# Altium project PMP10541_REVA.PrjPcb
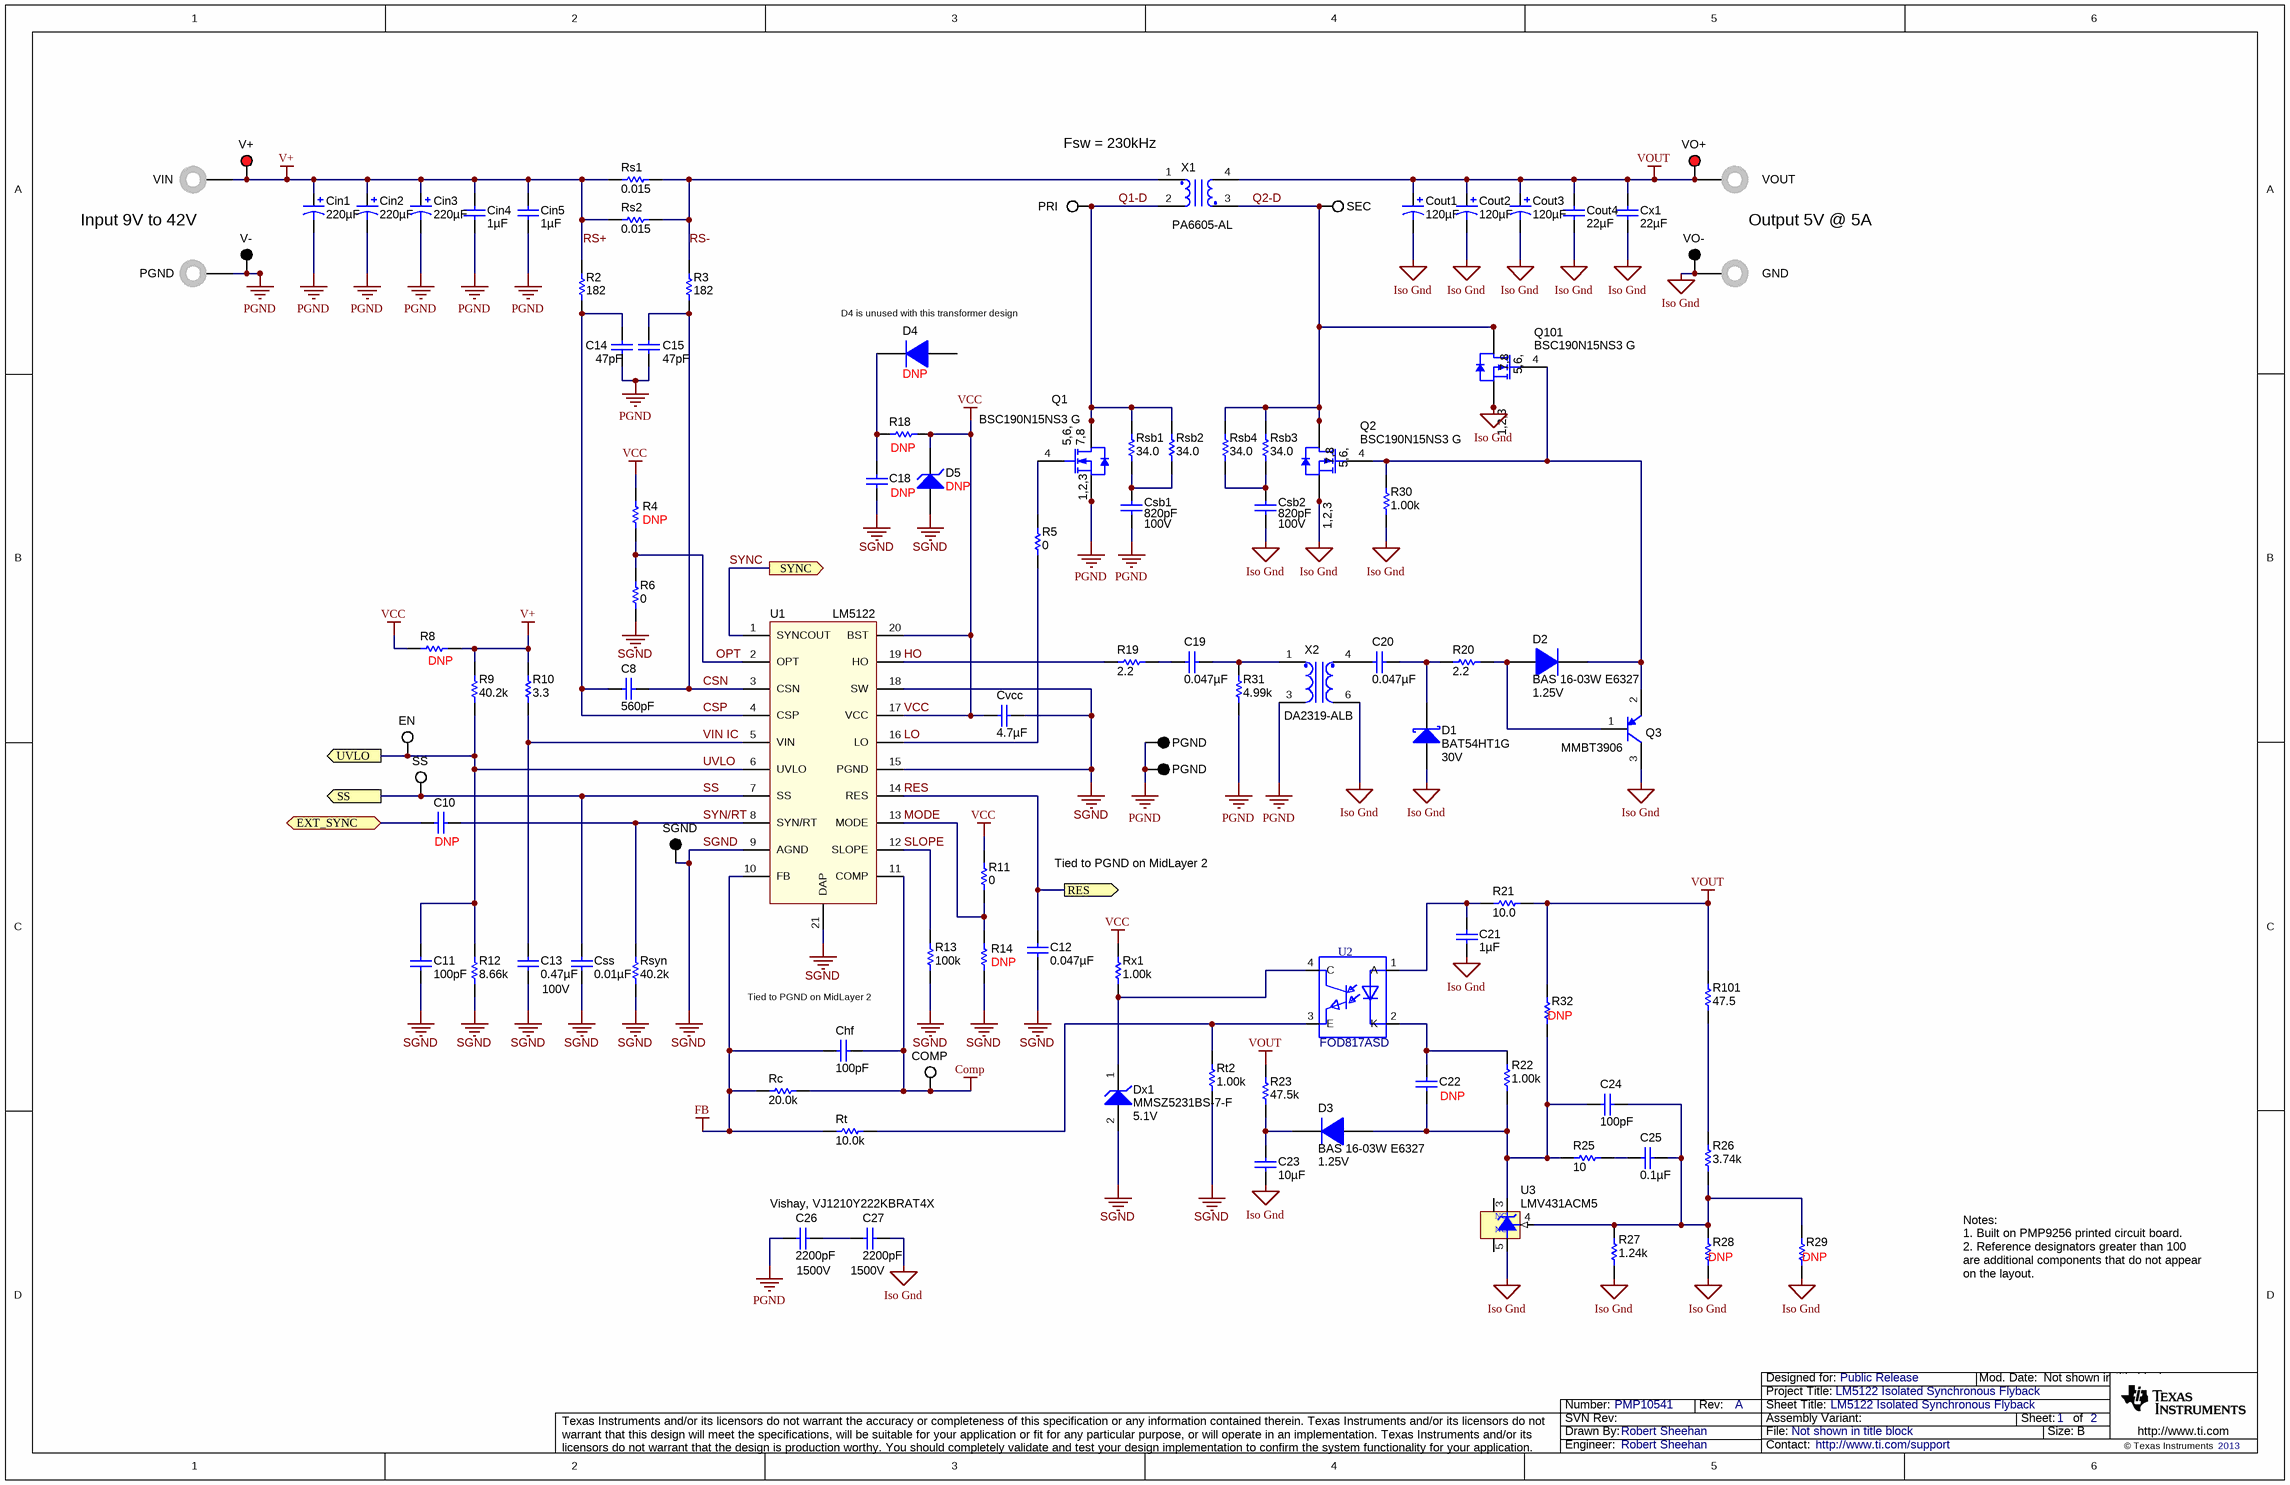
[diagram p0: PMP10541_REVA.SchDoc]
CopyrightYear: 2013; PCB_Layout: Jacen Schaedler; PCB_Rev: E1; PRJ_Customer: Public Release; PRJ_Engineer: Robert Sheehan; PRJ_Number: PMP10541; PRJ_Title: LM5122 Isolated Synchronous Flyback; SCH_Rev: A; TechSupport: http://www.ti.com/support
2 sheets, 118 parts. Net scope: flat (ports and power ports of the same name join across sheets).
Board file: PMP9256 Rev3.PcbDoc
Sheets:
  PMP10541_REVA.SchDoc
  Hardware_ANSI-B.SchDoc

## Sheet PMP10541_REVA.SchDoc: LM5122 Isolated Synchronous Flyback
size 431 x 279 mm; Date: Not shown in title block; ApprovedBy: David Baba; CheckedBy: Not shown in title block; Author: Not shown in title block; CompanyName: Not shown in title block; DrawnBy: Robert Sheehan; Engineer: Robert Sheehan; Organization: Not shown in title block; Address1: Not shown in title block; Address2: Not shown in title block; Address3: Not shown in title block; Address4: Not shown in title block; DocumentNumber: 1; Revision: Use project parameter SCH_Rev; SheetNumber: 1; SheetTotal: 2; PageSetup: Record=PageOptions¦CenterHorizontal=True¦CenterVertical=True¦PrintScale=0.96¦XCorrection=1.00¦YCorrection=1.00¦PrintKind=0¦BorderSize=5000000¦LeftOffset=0¦BottomOffset=0¦Orientation=2¦PaperLength=1000¦PaperWidth=1000¦Scale=100¦PaperSource=15¦PrintQuality=600¦MediaType=1¦DitherType=10¦PaperKind=11x17¦PrintScaleMode=1

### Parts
C8  ValueDisplayed: 560pF  [0603L]  (hidden comment: GRM1885C1H561JA01D)
C10  DNP  [0603L]
C11  ValueDisplayed: 100pF  [0603L]  (hidden comment: GRM1885C1H101JA01D)
C12  ValueDisplayed: 0.047µF  [0603L]  (hidden comment: GRM188R71E473KA01D)
C13  ValueDisplayed: 0.47µF  Value2: 100V  [0805L]  (hidden comment: GRM21BR72A474KA73L)
C14  ValueDisplayed: 47pF  [0603L]  (hidden comment: GRM1885C1H470JA01D)
C15  ValueDisplayed: 47pF  [0603L]  (hidden comment: GRM1885C1H470JA01D)
C18  DNP  [0805L]
C19  ValueDisplayed: 0.047µF  [0603L]  (hidden comment: GRM188R71E473KA01D)
C20  ValueDisplayed: 0.047µF  [0603L]  (hidden comment: GRM188R71E473KA01D)
C21  ValueDisplayed: 1µF  [0603L]  (hidden comment: C1608X7R1C105K)
C22  DNP  [0805L]
C23  ValueDisplayed: 10µF  [0805L]  (hidden comment: GRM21BR61C106KE15L)
C24  ValueDisplayed: 100pF  [0805L]  (hidden comment: 08051A101FAT2A)
C25  ValueDisplayed: 0.1µF  [0603L]  (hidden comment: GRM188R71H104KA93D)
C26  Vishay, VJ1210Y222KBRAT4X  ValueDisplayed: 2200pF  Value2: 1500V  [1210L]
C27  ValueDisplayed: 2200pF  Value2: 1500V  [1210L]  (hidden comment: VJ1210Y222KXGAT5Z)
Chf  ValueDisplayed: 100pF  [0603L]  (hidden comment: GRM1885C1H101JA01D)
Cin1  ValueDisplayed: 220µF  [SM_RADIAL_H13]  (hidden comment: EEV-FK1J221Q)
Cin2  ValueDisplayed: 220µF  [SM_RADIAL_H13]  (hidden comment: EEV-FK1J221Q)
Cin3  ValueDisplayed: 220µF  [SM_RADIAL_H13]  (hidden comment: EEV-FK1J221Q)
Cin4  ValueDisplayed: 1µF  [1206L]  (hidden comment: C3216X7R2A105M)
Cin5  ValueDisplayed: 1µF  [1206L]  (hidden comment: C3216X7R2A105M)
COMP  5002  [Keystone5002]  (value not drawn)
Cout1  ValueDisplayed: 120µF  [CAPSMT_62_F61]  (hidden comment: 20SVPF120M)
Cout2  ValueDisplayed: 120µF  [CAPSMT_62_F61]  (hidden comment: 20SVPF120M)
Cout3  ValueDisplayed: 120µF  [CAPSMT_62_F61]  (hidden comment: 20SVPF120M)
Cout4  ValueDisplayed: 22µF  [1206L]  (hidden comment: GRM31CR61C226KE15L)
Csb1  ValueDisplayed: 820pF  Value2: 100V  [0603L]  (hidden comment: GRM188R72A821KA01D)
Csb2  ValueDisplayed: 820pF  Value2: 100V  [0603L]  (hidden comment: GRM188R72A821KA01D)
Css  ValueDisplayed: 0.01µF  [0603L]  (hidden comment: GRM188R71H103KA01D)
Cvcc  ValueDisplayed: 4.7µF  [0603L]  (hidden comment: C0603C475K8PACTU)
Cx1  ValueDisplayed: 22µF  [1206L]  (hidden comment: GRM31CR61C226KE15L)
D1  BAT54HT1G  value 30V  [sod-323]
D2  BAS 16-03W E6327  value 1.25V  [sod-323]
D3  BAS 16-03W E6327  value 1.25V  [sod-323]
D4  DNP  [SOD-123]
D5  DNP  [SMA]
Dx1  MMSZ5231BS-7-F  value 5.1V  [sod-323]
EN  5002  [Keystone5002]  (value not drawn)
PGND  GND  [Keystone_575-4]
PGND2  PGND  [Keystone_575-4]
PGND3  PGND  [Keystone5011]
PGND4  PGND  [Keystone5011]
PRI  5002  [Keystone5002]  (value not drawn)
Q1  BSC190N15NS3 G  [PG-TDSON-8]
Q2  BSC190N15NS3 G  [PG-TDSON-8]
Q3  MMBT3906  [SOT-23]
Q101  BSC190N15NS3 G  [PG-TDSON-8]
R2  value 182  [0603L]  (hidden comment: CRCW0603182RFKEA)
R3  value 182  [0603L]  (hidden comment: CRCW0603182RFKEA)
R4  DNP  [0603L]
R5  value 0  [0603L]  (hidden comment: ERJ-3GEY0R00V)
R6  value 0  [0603L]  (hidden comment: ERJ-3GEY0R00V)
R8  DNP  [0603L]
R9  value 40.2k  [0603L]  (hidden comment: CRCW060340K2FKEA)
R10  value 3.3  [0603L]  (hidden comment: CRCW06033R30JNEA)
R11  value 0  [0603L]  (hidden comment: ERJ-3GEY0R00V)
R12  value 8.66k  [0603L]  (hidden comment: CRCW06038K66FKEA)
R13  value 100k  [0603L]  (hidden comment: CRCW0603100KFKEA)
R14  DNP  [0603L]
R18  DNP  [0603L]
R19  value 2.2  [0603L]  (hidden comment: CRCW06032R20JNEA)
R20  value 2.2  [0603L]  (hidden comment: CRCW06032R20JNEA)
R21  value 10.0  [0805L]  (hidden comment: CRCW080510R0FKEA)
R22  ValueDisplayed: 1.00k  [0603L]  (hidden comment: CRCW06031K00FKEA)
R23  value 47.5k  [0603L]  (hidden comment: CRCW060347K5FKEA)
R25  ValueDisplayed: 10  [0603L]  (hidden comment: CRCW060310R0JNEA)
R26  ValueDisplayed: 3.74k  [0603L]  (hidden comment: CRCW06033K74FKEA)
R27  ValueDisplayed: 1.24k  [0603L]  (hidden comment: CRCW06031K24FKEA)
R28  DNP  [0603L]
R29  DNP  [0603L]
R30  value 1.00k  [0603L]  (hidden comment: CRCW06031K00FKEA)
R31  value 4.99k  [0603L]  (hidden comment: CRCW06034K99FKEA)
R32  DNP  [0603L]
R101  ValueDisplayed: 47.5  [0603]  (hidden comment: CRCW060347R5FKEA)
Rc  value 20.0k  [0603L]  (hidden comment: CRCW060320K0FKEA)
Rs1  ValueDisplayed: 0.015  [2512]  (hidden comment: WSL2512R0150FEA)
Rs2  ValueDisplayed: 0.015  [2512]  (hidden comment: WSL2512R0150FEA)
Rsb1  value 34.0  [1210L]  (hidden comment: ERJ-14NF34R0U)
Rsb2  value 34.0  [1210L]  (hidden comment: ERJ-14NF34R0U)
Rsb3  value 34.0  [1210L]  (hidden comment: ERJ-14NF34R0U)
Rsb4  value 34.0  [1210L]  (hidden comment: ERJ-14NF34R0U)
Rsyn  value 40.2k  [0603L]  (hidden comment: CRCW060340K2FKEA)
Rt  value 10.0k  [0603L]  (hidden comment: CRCW060310K0FKEA)
Rt2  value 1.00k  [0603L]  (hidden comment: CRCW06031K00FKEA)
Rx1  value 1.00k  [0603L]  (hidden comment: CRCW06031K00FKEA)
SEC  5002  [Keystone5002]  (value not drawn)
SGND  SGND  [Keystone5001]  (value not drawn)
SS  5002  [Keystone5002]  (value not drawn)
U1  LM5122  [MXA20A_L]
U2  FOD817ASD  [FOD817AS]
U3  TI, LMV431ACM5  [MF05A_N]  (value not drawn)
V+  5010  [Keystone5010]  (value not drawn)
V-  5011  [Keystone5011]  (value not drawn)
VIN  575-4  [Keystone_575-4]  (value not drawn)
VO+  5010  [Keystone5010]  (value not drawn)
VO-  5011  [Keystone5011]  (value not drawn)
VOUT  Comment_1: Output 5V @ 5A  [Keystone_575-4]  (hidden comment: 575-4)
X1  PA6605-AL  [PA6605-AL]
X2  DA2319-ALB  [DA2319-ALB]

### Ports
EXT_SYNC, RES, SS, SYNC (out), UVLO

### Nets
Comp: Chf.1 COMP.1 Rc.2 U1.11(COMP)
FB: Chf.2 Rc.1 Rt.2 U1.10(FB)
Iso Gnd: C21.2 C23.2 C27.1 Cout1.2(-) Cout2.2(-) Cout3.2(-) Cout4.2 Csb2.2 Cx1.2 D1.2(A) PGND.1 Q2.1(S) Q2.2(S) Q2.3(S) Q3.3(C) Q101.1(S) Q101.2(S) Q101.3(S) R27.1 R28.1 R29.1 R30.1 U3.5(A) VO-.1 X2.6
PGND: C11.2 C12.2 C13.2 C14.1 C15.2 C18.2 C26.2 Cin1.2(-) Cin2.2(-) Cin3.2(-) Cin4.2 Cin5.2 Csb1.2 Css.2 Cvcc.1 D5.2(A) Dx1.2(A) PGND2.1 PGND3.1 PGND4.1 Q1.1(S) Q1.2(S) Q1.3(S) R6.1 R12.1 R13.1 R14.1 R31.1 Rsyn.1 Rt2.1 SGND.1 U1.9(AGND) U1.15(PGND) U1.18(SW) U1.21(DAP) V-.1 X2.3
V+: Cin1.1(+) Cin2.1(+) Cin3.1(+) Cin4.1 Cin5.1 R2.2 R8.1 R9.2 R10.2 Rs1.1 Rs2.1 V+.1 VIN.1
VCC: Cvcc.2 D5.1(K) R4.2 R8.2 R11.2 R18.1 Rx1.2 U1.17(VCC) U1.20(BST)
VOUT: Cout1.1(+) Cout2.1(+) Cout3.1(+) Cout4.1 Cx1.1 R21.2 R23.2 R32.1 R101.2 VO+.1 VOUT.1 X1.4
CSN: C8.1 C15.1 R3.1 U1.3(CSN)
CSP: C8.2 C14.2 R2.1 U1.4(CSP)
EXT_SYNC: C10.2 ; port EXT_SYNC
HO: R19.2 U1.19(HO)
LO: R5.2 U1.16(LO)
MODE: R11.1 R14.2 U1.13(MODE)
OPT: R4.1 R6.2 U1.2(OPT)
Q1-D: PRI.1 Q1.5(D) Q1.6(D) Q1.7(D) Q1.8(D) Q1.9(D) Rsb1.2 Rsb2.2 X1.2
Q2-D: Q2.5(D) Q2.6(D) Q2.7(D) Q2.8(D) Q2.9(D) Q101.5(D) Q101.6(D) Q101.7(D) Q101.8(D) Q101.9(D) Rsb3.2 Rsb4.2 SEC.1 X1.3
RES: C12.1 U1.14(RES) ; port RES
RS-: R3.2 Rs1.2 Rs2.2 X1.1
SLOPE: R13.2 U1.12(SLOPE)
SS: Css.1 SS.1 U1.7(SS) ; port SS
SYN/RT: C10.1 Rsyn.2 U1.8(SYN/RT)
SYNC: U1.1(SYNCOUT) ; port SYNC
UVLO: C11.1 EN.1 R9.1 R12.2 U1.6(UVLO) ; port UVLO
VIN IC: C13.1 R10.1 U1.5(VIN)
NetC18_1: C18.1 D4.1(K) R18.2
NetC19_1: C19.1 R19.1
NetC19_2: C19.2 R31.2 X2.1
NetC20_1: C20.1 X2.4
NetC20_2: C20.2 D1.1(K) R20.1
NetC21_1: C21.1 R21.1 U2.1(A)
NetC22_1: C22.1 C24.1 D3.2(A) R22.1 R25.1 R32.2 U3.3(K)
NetC22_2: C22.2 R22.2 U2.2(K)
NetC23_1: C23.1 D3.1(K) R23.1
NetC24_2: C24.2 C25.1 R26.1 R27.2 R28.2 R29.2 U3.4(REF)
NetC25_2: C25.2 R25.2
NetC26_1: C26.1 C27.2
NetCsb1_1: Csb1.1 Rsb1.1 Rsb2.1
NetCsb2_1: Csb2.1 Rsb3.1 Rsb4.1
NetD2_1: D2.1(K) Q2.4(G) Q3.2(E) Q101.4(G) R30.2
NetD2_2: D2.2(A) Q3.1(B) R20.2
NetDx1_1: Dx1.1(K) Rx1.1 U2.4(C)
NetQ1_4: Q1.4(G) R5.1
NetR26_2: R26.2 R101.1
NetRt_1: Rt.1 Rt2.2 U2.3(E)

Not connected (* = marked no-connect by the designer): D4 2(A); U3 1(NC) 2(NC)

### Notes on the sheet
- (near X1) Fsw = 230kHz
- Input 9V to 42V
- RS+
- (near D4) D4 is unused with this transformer design
- SGND
- Tied to PGND on MidLayer 2
- (near COMP) SGND
- Notes:
  1. Built on PMP9256 printed circuit board.
  2. Reference designators greater than 100 are additional components that do not appear on the layout.

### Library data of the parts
C8 = GRM1885C1H561JA01D: CAP, CERM, 560pF, 50V, +/-5%, C0G/NP0, 0603; Manufacturer: MuRata; Polarized: N; CompType: Capacitor; U/M: EA; Cap_F: 0.00000000056; Tolerance_%: 5; Value1: Unknown; VDC_V: 50; TaMin_C: -55; TaMax_C: 125; Cap_Case: 0603
C10 = GRM1885C1H101JA01D: CAP, CERM, 100 pF, 50 V, +/- 5%, C0G/NP0, 0603; Manufacturer: MuRata; Polarized: N; CompType: Capacitor; Value: 100pF; U/M: EA; Cap_F: 0.0000000001; Tolerance_%: 5; Value1: Unknown; VDC_V: 50; Value2: 50V; TaMin_C: -55; TaMax_C: 125; Cap_Case: 0603
C11 Chf = GRM1885C1H101JA01D: CAP, CERM, 100pF, 50V, +/-5%, C0G/NP0, 0603; Manufacturer: MuRata; Polarized: N; CompType: Capacitor; U/M: EA; Cap_F: 0.0000000001; Tolerance_%: 5; VDC_V: 50; TaMin_C: -55; TaMax_C: 125; Cap_Case: 0603
C12 C19 C20 = GRM188R71E473KA01D: CAP, CERM, 0.047uF, 25V, +/-10%, X7R, 0603; Manufacturer: MuRata; Polarized: N; CompType: Capacitor; U/M: EA; Cap_F: 0.000000047; Tolerance_%: 10; VDC_V: 25; TaMin_C: -55; TaMax_C: 125; Cap_Case: 0603
C13 = GRM21BR72A474KA73L: CAP, CERM, 0.47uF, 100V, +/-10%, X7R, 0805; Manufacturer: MuRata; Polarized: N; CompType: Capacitor; U/M: EA; Cap_F: 0.00000047; Tolerance_%: 10; Value1: Unknown; VDC_V: 100; TaMin_C: -55; TaMax_C: 125; Cap_Case: 0805
C14 C15 = GRM1885C1H470JA01D: CAP, CERM, 47pF, 50V, +/-5%, C0G/NP0, 0603; Manufacturer: MuRata; Polarized: N; CompType: Capacitor; U/M: EA; Cap_F: 0.000000000047; Tolerance_%: 5; Value1: Unknown; VDC_V: 50; TaMin_C: -55; TaMax_C: 125; Cap_Case: 0603
C18 = GRM21BR61C106KE15L: CAP, CERM, 10uF, 16V, +/-10%, X5R, 0805; Manufacturer: MuRata; Polarized: N; CompType: Capacitor; ValueDisplayed: 10µF; U/M: EA; Cap_F: 0.00001; Tolerance_%: 10; ESR_Ohm: 0.008; Value1: 0.008 ohm; VDC_V: 16; TaMin_C: -55; TaMax_C: 85; Cap_Case: 0805
C21 = C1608X7R1C105K: CAP, CERM, 1uF, 16V, +/-10%, X7R, 0603; Manufacturer: TDK; Polarized: N; CompType: Capacitor; U/M: EA; Cap_F: 0.000001; Tolerance_%: 10; ESR_Ohm: 0.0057; Value1: 0.0057 ohm; VDC_V: 16; TaMin_C: -55; TaMax_C: 125; Cap_Case: 0603
C22 = C2012Y5V1H105Z: Capacitor; Manufacturer: TDK; Cap_Case: 0805; Polarized: N; Tolerance_%: 80; VDC_V: 50; Cap_F: 1.0E-6; Value: 100pF; Value1: Ohm; Value2: 50V; Dielectric: Y5V
C23 = GRM21BR61C106KE15L: CAP, CERM, 10uF, 16V, +/-10%, X5R, 0805; Manufacturer: MuRata; Polarized: N; CompType: Capacitor; U/M: EA; Cap_F: 0.00001; Tolerance_%: 10; ESR_Ohm: 0.008; Value1: 0.008 ohm; VDC_V: 16; TaMin_C: -55; TaMax_C: 85; Cap_Case: 0805
C24 = 08051A101FAT2A: CAP, CERM, 100pF, 100V, +/-1%, C0G/NP0, 0805; Manufacturer: AVX; Polarized: N; CompType: Capacitor; U/M: EA; Cap_F: 0.0000000001; Tolerance_%: 1; ESR_Ohm: 0.356; Value1: 0.356 ohm; VDC_V: 100; TaMin_C: -55; TaMax_C: 125; Cap_Case: 0805
C25 = GRM188R71H104KA93D: CAP, CERM, 0.1uF, 50V, +/-10%, X7R, 0603; Manufacturer: MuRata; Polarized: N; CompType: Capacitor; U/M: EA; Cap_F: 0.0000001; Tolerance_%: 10; Value1: Unknown; VDC_V: 50; TaMin_C: -55; TaMax_C: 125; Cap_Case: 0603
C26 C27 = VJ1210Y222KXGAT5Z: CAP, CERM, 2200pF, 1000V, +/-10%, X7R, 1210; Manufacturer: Vishay-Vitramon; Polarized: N; CompType: Capacitor; U/M: EA; Cap_F: 0.0000000022; Tolerance_%: 10; VDC_V: 1000; TaMin_C: -55; TaMax_C: 125; Cap_Case: 1210
Cin1-Cin3 = EEV-FK1J221Q: CAP, AL, 220uF, 63V, +/-20%, 0.16 ohm, SMD; Manufacturer: Panasonic; Polarized: Y; CompType: Capacitor; U/M: EA; Cap_F: 0.00022; Tolerance_%: 20; VDC_V: 63; ESR_Ohm: 0.16; IRMS_A: 0.8; TaMin_C: -55; TaMax_C: 105; Cap_Case: H13
Cin4 Cin5 = C3216X7R2A105M: CAP, CERM, 1uF, 100V, +/-20%, C Series, 1206; Manufacturer: TDK; Polarized: N; CompType: Capacitor; U/M: EA; Cap_F: 0.000001; Tolerance_%: 20; ESR_Ohm: 0.006; Value1: 0.006 ohm; VDC_V: 100; IRMS_A: 4.5; TaMin_C: -55; TaMax_C: 125; Cap_Case: 1206
COMP EN SS = 5002: Test Point, TH, Miniature, White; Manufacturer: Keystone; CompType: Test Point Loop; U/M: EA
Cout1-Cout3 = 20SVPF120M: CAP, AL, 120uF, 20V, +/-20%, 0.025 ohm, SMD; Manufacturer: Sanyo; Polarized: Y; CompType: Capacitor; U/M: EA; Cap_F: 0.00012; Tolerance_%: 20; ESR_Ohm: 0.025; IRMS_A: 3.2; TaMin_C: -55; TaMax_C: 105
Cout4 Cx1 = GRM31CR61C226KE15L: CAP, CERM, 22uF, 16V, +/-10%, X5R, 1206; Manufacturer: MuRata; Polarized: N; CompType: Capacitor; U/M: EA; Cap_F: 0.000022; Tolerance_%: 10; Value1: Unknown; VDC_V: 16; TaMin_C: -55; TaMax_C: 85; Cap_Case: 1206
Csb1 Csb2 = GRM188R72A821KA01D: CAP, CERM, 820pF, 100V, +/-10%, X7R, 0603; Manufacturer: MuRata; Polarized: N; CompType: Capacitor; U/M: EA; Cap_F: 0.00000000082; Tolerance_%: 10; Value1: Unknown; VDC_V: 100; TaMin_C: -55; TaMax_C: 125; Cap_Case: 0603
Css = GRM188R71H103KA01D: CAP, CERM, 0.01uF, 50V, +/-10%, X7R, 0603; Manufacturer: MuRata; Polarized: N; CompType: Capacitor; U/M: EA; Cap_F: 0.00000001; Tolerance_%: 10; Value1: Unknown; VDC_V: 50; TaMin_C: -55; TaMax_C: 125; Cap_Case: 0603
Cvcc = C0603C475K8PACTU: CAP, CERM, 4.7uF, 10V, +/-10%, X5R, 0603; Manufacturer: Kemet; Polarized: N; CompType: Capacitor; U/M: EA; Cap_F: 0.0000047; Tolerance_%: 10; ESR_Ohm: 0.006; Value1: 0.006 ohm; IRMS_A: 7.24; TaMin_C: -55; TaMax_C: 85; Cap_Case: 0603
D1 = BAT54HT1G: Diode, Schottky, 30V, 0.2A, SOD-323; Manufacturer: ON Semiconductor; U/M: EA; Vf_V: 0.35; Value2: 0.35V; Io_A: 0.2; Vr_V: 30
D2 D3 = Diode: DIODE SWITCH 80V 0.25A SOD323-2; Manufacturer: Infineon Technologies; U/M: EA; Io_A: 0.25; Vf_V: 1.25; Vr_V: 80
D4 = BAV21W-7-F: Diode, Switching, 200V, 0.2A, SOD-123; Manufacturer: Diodes Inc.; U/M: EA; Vf_V: 1.25; Value2: 1.25V; Io_A: 0.2; Vr_V: 200; TJmax_C: 150
D5 = BZG03C15G: Diode, Zener, 15 V, 1.5 W, SMA; Manufacturer: ON Semiconductor; Value: 15V; U/M: EA; Power_W: 1.5; Vz_V: 15; Value1: 1.5W; SymbolCreator: a0412235
Dx1 = MMSZ5231BS-7-F: Diode, Zener, 5.1V, 200mW, SOD-323; Manufacturer: Diodes Inc.; U/M: EA; Power_W: 0.2; Vz_V: 5.1; Value1: 0.2W; RJA_CperW: 350
PGND PGND2 VIN VOUT = 575-4: Standard Banana Jack, Uninsulated, 5.5mm; Manufacturer: Keystone; CompType: Connector; U/M: EA
PGND3 PGND4 V- VO- = 5011: Test Point, TH, Multipurpose, Black; Manufacturer: Keystone; CompType: Test Point Loop; U/M: EA
PRI SEC = 5002: Test Point, Miniature, White, TH; Manufacturer: Keystone; CompType: Test Point Loop; U/M: EA
Q1 Q2 Q101 = BSC190N15NS3 G: MOSFET, N-CH, 150V, 50A, PG-TDSON-8; Manufacturer: Infineon Technologies; Alternate Manufacturer: None; U/M: EA; ChType: N; VdsMax_V: 150; Value1: 0.02 ohm; Rdson45_Ohm: 0.02; Value2: 23 nC; QgTyp_nC: 23; Vgs_V: 20; IdsMax_A: 50
Q3 = MMBT3906, Fairchild Semiconductor: Transistor, PNP, 40V, 0.2A, SOT-23; Alternate Manufacturer: None; CompType: BJT; U/M: EA; PNP: 1; NPN: 0; Vceo_V: 40; Vcesat1_V: 0.25; Value: 0.25V; IcRated_A: 0.2; HfeMax: 300
R2 R3 = CRCW0603182RFKEA: RES, 182 ohm, 1%, 0.1W, 0603; Manufacturer: Vishay-Dale; CompType: Resistor; Value_Code: 182R; Tolerance_%: 1; Power_W: 0.1; VDC_V: 75; TempCo: 100 ppm/C; EIA_Code: E96; U/M: EA
R4 = CRCW0603158KFKEA: RES, 158 k, 1%, 0.1 W, 0603; Manufacturer: Vishay-Dale; CompType: Resistor; Value: 158k; Res_ohm: 158000; Tolerance_%: 1; Power_W: 0.1; Value2: 0.1W; VDC_V: 75; TempCo: 100 ppm/C; EIA_Code: E96; U/M: EA
R5 R6 R11 = ERJ-3GEY0R00V: RES, 0 ohm, 5%, 0.1W, 0603; Manufacturer: Panasonic; CompType: Resistor; Value_Code: 0000; Tolerance_%: 5; Power_W: 0.1; VDC_V: 50; TempCo: 600 ppm/C; EIA_Code: E24; U/M: EA
R8 R14 = ERJ-3GEY0R00V: RES, 0, 5%, 0.1 W, 0603; Manufacturer: Panasonic; CompType: Resistor; Value: 0; Value_Code: 0000; Tolerance_%: 5; Power_W: 0.1; Value2: 0.1W; VDC_V: 50; TempCo: 600 ppm/C; EIA_Code: E24; U/M: EA
R9 Rsyn = CRCW060340K2FKEA: RES, 40.2k ohm, 1%, 0.1W, 0603; Manufacturer: Vishay-Dale; CompType: Resistor; Res_ohm: 40200; Value_Code: 40k2; Tolerance_%: 1; Power_W: 0.1; VDC_V: 75; TempCo: 100 ppm/C; EIA_Code: E96; U/M: EA
R10 = CRCW06033R30JNEA: RES, 3.3 ohm, 5%, 0.1W, 0603; Manufacturer: Vishay-Dale; CompType: Resistor; Value_Code: 3R30; Tolerance_%: 5; Power_W: 0.1; VDC_V: 75; TempCo: 200 ppm/C; EIA_Code: E24; U/M: EA
R12 = CRCW06038K66FKEA: RES, 8.66k ohm, 1%, 0.1W, 0603; Manufacturer: Vishay-Dale; CompType: Resistor; Res_ohm: 8660; Value_Code: 8k66; Tolerance_%: 1; Power_W: 0.1; VDC_V: 75; TempCo: 100 ppm/C; EIA_Code: E96; U/M: EA
R13 = CRCW0603100KFKEA: RES, 100k ohm, 1%, 0.1W, 0603; Manufacturer: Vishay-Dale; CompType: Resistor; Res_ohm: 100000; Tolerance_%: 1; Power_W: 0.1; VDC_V: 75; TempCo: 100 ppm/C; EIA_Code: E96; U/M: EA
R18 = CRCW06030000Z0EA: RES, 0 ohm, 5%, 0.1W, 0603; Manufacturer: Vishay-Dale; Alternate Manufacturer: Any; Alternate PartNumber: Equivalent; CompType: Resistor; Value: 0; Value_Code: 0000; Tolerance_%: 5; Power_W: 0.1; VDC_V: 75; TempCo: 200 ppm/C; EIA_Code: E24; U/M: EA
R19 R20 = CRCW06032R20JNEA: RES, 2.2 ohm, 5%, 0.1W, 0603; Manufacturer: Vishay-Dale; CompType: Resistor; Value_Code: 2R20; Tolerance_%: 5; Power_W: 0.1; VDC_V: 75; TempCo: 200 ppm/C; EIA_Code: E24; U/M: EA
R21 = CRCW080510R0FKEA: RES, 10.0 ohm, 1%, 0.125W, 0805; Manufacturer: Vishay-Dale; CompType: Resistor; Res_ohm: 10; Value_Code: 10R0; Tolerance_%: 1; Power_W: 0.125; VDC_V: 150; TempCo: 100 ppm/C; EIA_Code: E96; U/M: EA
R22 = CRCW06031K00FKEA: RES, 1.00 k, 1%, 0.1 W, 0603; Manufacturer: Vishay-Dale; CompType: Resistor; Value: 1.00k; Res_ohm: 1000; Value_Code: 1k00; Tolerance_%: 1; Power_W: 0.1; Value2: 0.1W; VDC_V: 75; TempCo: 100 ppm/C; EIA_Code: E96; U/M: EA
R23 = CRCW060347K5FKEA: RES, 47.5k ohm, 1%, 0.1W, 0603; Manufacturer: Vishay-Dale; CompType: Resistor; Res_ohm: 47500; Value_Code: 47k5; Tolerance_%: 1; Power_W: 0.1; VDC_V: 75; TempCo: 100 ppm/C; EIA_Code: E96; U/M: EA
R25 = CRCW060310R0JNEA: RES, 10, 5%, 0.1 W, 0603; Manufacturer: Vishay-Dale; CompType: Resistor; Value: 10; Value_Code: 10R0; Tolerance_%: 5; Power_W: 0.1; Value2: 0.1W; VDC_V: 75; TempCo: 200 ppm/C; EIA_Code: E24; U/M: EA
R26 = CRCW06033K74FKEA: RES, 3.74 k, 1%, 0.1 W, 0603; Manufacturer: Vishay-Dale; CompType: Resistor; Value: 3.74k; Res_ohm: 3740; Value_Code: 3k74; Tolerance_%: 1; Power_W: 0.1; Value2: 0.1W; VDC_V: 75; TempCo: 100 ppm/C; EIA_Code: E96; U/M: EA
R27 = CRCW06031K24FKEA: RES, 1.24 k, 1%, 0.1 W, 0603; Manufacturer: Vishay-Dale; CompType: Resistor; Value: 1.24k; Res_ohm: 1240; Value_Code: 1k24; Tolerance_%: 1; Power_W: 0.1; Value2: 0.1W; VDC_V: 75; TempCo: 100 ppm/C; EIA_Code: E96; U/M: EA
R28 = CRCW06032K26FKEA: RES, 2.26k ohm, 1%, 0.1W, 0603; Manufacturer: Vishay-Dale; CompType: Resistor; Res_ohm: 2260; Value_Code: 2k26; Tolerance_%: 1; Power_W: 0.1; VDC_V: 75; TempCo: 100 ppm/C; EIA_Code: E96; U/M: EA
R29 = CRCW0603442RFKEA: RES, 442 ohm, 1%, 0.1W, 0603; Manufacturer: Vishay-Dale; CompType: Resistor; Value: 442; Value_Code: 442R; Tolerance_%: 1; Power_W: 0.1; VDC_V: 75; TempCo: 100 ppm/C; EIA_Code: E96; U/M: EA
R30 Rt2 Rx1 = CRCW06031K00FKEA: RES, 1.00k ohm, 1%, 0.1W, 0603; Manufacturer: Vishay-Dale; CompType: Resistor; Res_ohm: 1000; Value_Code: 1k00; Tolerance_%: 1; Power_W: 0.1; VDC_V: 75; TempCo: 100 ppm/C; EIA_Code: E96; U/M: EA
R31 = CRCW06034K99FKEA: RES, 4.99k ohm, 1%, 0.1W, 0603; Manufacturer: Vishay-Dale; CompType: Resistor; Res_ohm: 4990; Value_Code: 4k99; Tolerance_%: 1; Power_W: 0.1; VDC_V: 75; TempCo: 100 ppm/C; EIA_Code: E96; U/M: EA
R32 Rt = CRCW060310K0FKEA: RES, 10.0k ohm, 1%, 0.1W, 0603; Manufacturer: Vishay-Dale; CompType: Resistor; Res_ohm: 10000; Value_Code: 10k0; Tolerance_%: 1; Power_W: 0.1; VDC_V: 75; TempCo: 100 ppm/C; EIA_Code: E96; U/M: EA
R101 = CRCW060347R5FKEA: RES, 47.5, 1%, 0.1 W, 0603; Manufacturer: Vishay-Dale; CompType: Resistor; Value: 47.5; Value_Code: 47R5; Tolerance_%: 1; Power_W: 0.1; Value2: 0.1W; VDC_V: 75; TempCo: 100 ppm/C; EIA_Code: E96; U/M: EA
Rc = CRCW060320K0FKEA: RES, 20.0k ohm, 1%, 0.1W, 0603; Manufacturer: Vishay-Dale; CompType: Resistor; Res_ohm: 20000; Value_Code: 20k0; Tolerance_%: 1; Power_W: 0.1; VDC_V: 75; TempCo: 100 ppm/C; EIA_Code: E96; U/M: EA
Rs1 Rs2 = WSL2512R0150FEA: RES, 0.015, 1%, 1 W, 2512; Manufacturer: Vishay-Dale; CompType: Resistor; Value: 0.015; Value_Code: R015; Tolerance_%: 1; Value2: 1W; TempCo: 75 ppm/C; EIA_Code: E96; U/M: EA
Rsb1-Rsb4 = MCR25JZHJ000: RES 34 OHM 1/2W 1% 1210 SMD; Manufacturer: Panasonic Electronic Components; CompType: Resistor; Res_ohm: 34; Value_Code: 0034; Tolerance_%: 1; Power_W: .5; Value2: 0.5W; VDC_V: 200; TempCo: 20 ppm/C; EIA_Code: E24; U/M: EA
SGND = 5001: Test Point, TH, Miniature, Black; Manufacturer: Keystone; CompType: Test Point Loop; U/M: EA
U1 = LM5122: Manufacturer: TI; PartNumber: LM5122MH; SymbolCreator: bkinsc; CompType: IC; U/M: EA
U2 = FOD817ASD: IC, Optocoupler, 5000V, 80-160% CTR; Manufacturer: Fairchild Optoelectronics Group; Value: FODA817ASD; Area: 93500; PCB DECAL: SMT_4PDIP
U3 = LMV431ACM5: Low-Voltage (1.24V) Adjustable Precision Shunt Regulator, 5-pin SOT-23; Manufacturer: National Semiconductor; PackageTopMarking: N09A*XTT; PowerWise: N; CompType: MiscPower
V+ VO+ = 5010: Test Point, Multipurpose, Red, TH; Manufacturer: Keystone; CompType: Test Point Loop; U/M: EA
X1 = PA6605: Manufacturer: Coilcraft Inc; SymbolVersion: use current date i.e. 2008-05-20; SymbolCreator: Use a-id; CompType: Transformer; U/M: EA, IN, or GM
X2 = DA2319-ALB: SMT Gate Drive Transformer; Manufacturer: Coilcraft; SymbolVersion: use current date i.e. 2008-05-20; SymbolCreator: Use a-id; U/M: EA

## Sheet Hardware_ANSI-B.SchDoc
size 431 x 279 mm; Date: Not shown in title block; ApprovedBy: Not shown in title block; CheckedBy: Not shown in title block; Author: Not shown in title block; CompanyName: Not shown in title block; Engineer: Not shown in title block; Organization: Not shown in title block; Address1: Not shown in title block; Address2: Not shown in title block; Address3: Not shown in title block; Address4: Not shown in title block; DocumentNumber: 2; Revision: Use project parameter SCH_Rev; SheetNumber: 2; SheetTotal: 2; PageSetup: Record=PageOptions¦CenterHorizontal=True¦CenterVertical=True¦PrintScale=1.00¦XCorrection=1.00¦YCorrection=1.00¦PrintKind=0¦BorderSize=5000000¦LeftOffset=0¦BottomOffset=0¦Orientation=2¦PaperLength=1000¦PaperWidth=1000¦Scale=100¦PaperSource=15¦PrintQuality=600¦MediaType=1¦DitherType=10¦PaperKind=Letter¦PrintScaleMode=1
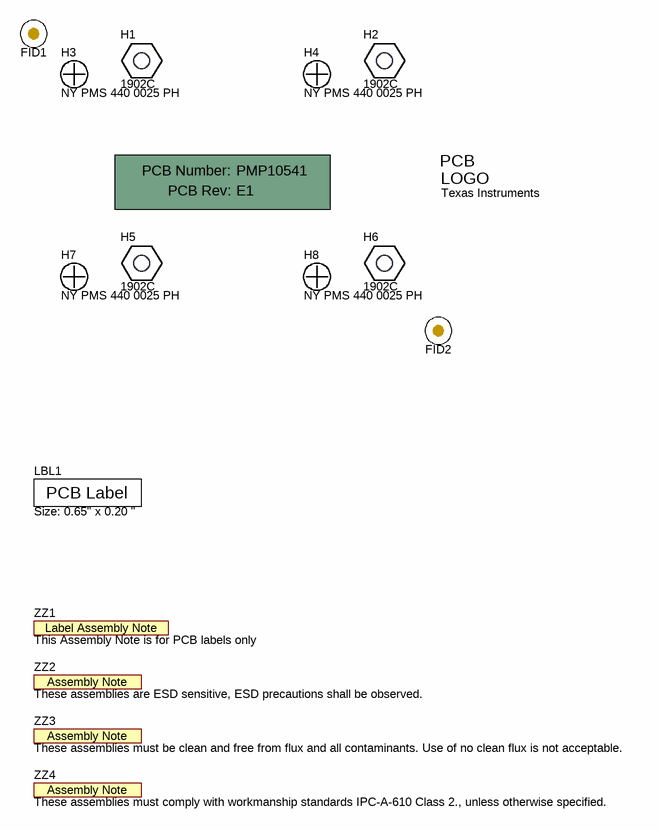
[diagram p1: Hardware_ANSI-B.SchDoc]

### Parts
!PCB1  Printed Circuit Board  (value not drawn)  (mechanical)
FID1  Fiducial  [Fiducial10-20]  (value not drawn)
FID2  Fiducial  [Fiducial10-20]  (value not drawn)
H1  1902C  [Keystone_1902C]
H2  1902C  [Keystone_1902C]
H3  NY PMS 440 0025 PH  [NY PMS 440 0025 PH]
H4  NY PMS 440 0025 PH  [NY PMS 440 0025 PH]
H5  1902C  [Keystone_1902C]
H6  1902C  [Keystone_1902C]
H7  NY PMS 440 0025 PH  [NY PMS 440 0025 PH]
H8  NY PMS 440 0025 PH  [NY PMS 440 0025 PH]
LBL1  Size: 0.65" x 0.20 "  [Label_650x200]
Logo1  Texas Instruments  [TI_Stacked_Overlay_Small]  (no BOM)
ZZ1  This Assembly Note is for PCB labels only  [AssemblyNoteLabel]  (no BOM)
ZZ2  These assemblies are ESD sensitive, ESD precautions shall be observed.  [AssemblyNote]  (no BOM)
ZZ3  These assemblies must be clean and free from flux and all contaminants. Use of no clean flux is not acceptable.  [AssemblyNote]  (no BOM)
ZZ4  These assemblies must comply with workmanship standards IPC-A-610 Class 2., unless otherwise specified.  [AssemblyNote]  (no BOM)

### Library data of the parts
!PCB1 = PCB: Manufacturer: Any; PartNumber: PMP9256; SymbolCreator: a0412235
FID1 FID2 = Fiducial: Fiducial mark.  There is nothing to buy or mount.; SymbolCreator: codlsc
H1 H2 H5 H6 = 1902C: Standoff, Hex, 0.5"L #4-40 Nylon; Manufacturer: Keystone; CompType: Hardware
H3 H4 H7 H8 = NY PMS 440 0025 PH: Machine Screw, Round, #4-40 x 1/4, Nylon, Philips panhead; Manufacturer: B&F Fastener Supply; CompType: Hardware; SymbolCreator: codlsc; U/M: EA
LBL1 = THT-14-423-10: Thermal Transfer Printable Labels, 0.650" W x 0.200" H - 10,000 per roll; Manufacturer: Brady; SymbolCreator: a0412235; CompType: Label
Logo1 = TI_Logo: Texas Instrument Corporate Signature; SymbolCreator: codlsc
ZZ1 = AssemblyNoteLabel: SymbolCreator: a0412235
ZZ2-ZZ4 = AssemblyNote: SymbolCreator: codlsc

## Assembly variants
001: not fitted C10 C18 C22 D4 D5 R4 R8 R14 R18 R28 R29 R32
